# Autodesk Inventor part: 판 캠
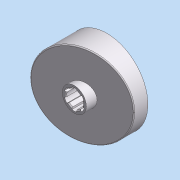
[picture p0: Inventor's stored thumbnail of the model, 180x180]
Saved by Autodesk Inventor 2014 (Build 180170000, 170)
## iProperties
Created: 2012-05
Part Number: 판 캠
Document SubType Name: 모델링
Designer: SeoGD™
Material: 일반
Appearance: 알루미늄 - 평지
변환 표준: STEP AP214IS
파일 이름: C:\Users\SeoGD\Desktop\?쒗뿕\??stp
전처리기: Build: 253, Release: 2010 SP1 - Date: Wed 07/29/2009
전송 단위: 밀리미터
불확실성: 0.01
Author: SeoGD™
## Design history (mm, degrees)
node "작업 평면4"
sketch "스케치1"
  geometry: C1 r 44.5 at (0, 0); 1 further point
  constraints: 1 centre point, 1 coincident
  dimensions: "d25" = 89 diameter of C1
extrude "돌출1" new body sketch "스케치1" distance "d1" = 40; taper "d2" = 0 deg
sketch "스케치2"
  geometry: L1 (-44.5, 15)-(44.5, 38.847); L2 (-44.5, 0)-(-44.5, 40) reference; L3 (-44.5, 40)-(44.5, 40) reference; L4 (44.5, 0)-(44.5, 40) reference; 1 further point
  constraints: 2 end point, 2 point on line
  dimensions: "d26" = 15 distance of L2.start L1.start; "d27" = 75 deg angle of L1 L2
extrude "돌출2" cut sketch "스케치2" stored distance "d5" = 40; taper "d6" = 0 deg
node "작업 평면1"
sketch "스케치3"
  geometry: C1 r 13 at (0, 0); 1 further point
  constraints: 1 centre point, 1 coincident
  dimensions: "d9" = 26 diameter of C1
extrude "돌출3" join sketch "스케치3" distance "d10" = 38; taper "d11" = 0 deg
hole "구멍1" diameter "d14" = 18; stored, may be unused: countersink angle "d18" = 90 deg, drill point angle "d20" = 118 deg; dims "d12" = 10, "d13" = 10, "d15" = 6, "d16" = 4, "d17" = 2, "d19" = 8
feature "쉘2" dims "d29" = 5
sketch "스케치6"
  geometry: C1 r 17.5 at (0, 0); C2 r 14 at (0, 0) reference; 1 further point
  constraints: 1 centre point, 1 coincident
  dimensions: "d28" = 35 diameter of C1
extrude "돌출4" join sketch "스케치6" stored distance "d30" = 38; taper "d31" = 0 deg
fillet "모깎기1" dims "d32" = 3
chamfer "모따기1" distance "d21" = 1; stored, may be unused: second distance "d22" = 2, angle "d23" = 45 deg
sketch "스케치7"
  geometry: L1 (-12.374, 12.374)-(-27.931, 27.931); A1 r 39.5 centre (0, 0) between (-27.931, 27.931) and (0, 39.5) reference; 2 further points
  constraints: 2 end point, 2 point on circle, 1 point on line, 1 vertical alignment, 2 other
  dimensions: "d33" = 45 deg dimension on point (0, 0) L1.start A1.end
feature "리브1" sketch "스케치7" dims "d34" = 5, "d35" = 1, "d36" = 0
fillet "모깎기2" dims "d37" = 3
sketch "스케치8"
  geometry: L1 (2.5, 10.712)-(2.5, 8.646); L2 (-2.5, 10.712)-(-2.5, 8.646); A1 r 11 centre (0, 0) between (2.5, 10.712) and (-2.5, 10.712); A2 r 9 centre (0, 0) between (2.5, 8.646) and (-2.5, 8.646) reference; 1 further point
  constraints: 4 end point, 4 point on circle, 2 parallel, 1 centre point, 1 coincident, 1 vertical
  dimensions: "d41" = 22 diameter of A1; "d42" = 5 distance between parallel lines of L1 L2
extrude "돌출5" cut sketch "스케치8" stored distance "d43" = 38; taper "d44" = 0 deg
fillet "모깎기3" dims "d48" = 1
node "솔리드1"
node "솔리드 본체"
node "곡면 본체"
pattern_circular "원형 패턴1" dims angle "d39" = 360 deg
pattern_circular "원형 패턴2" dims angle "d46" = 360 deg
node "솔리드2"
